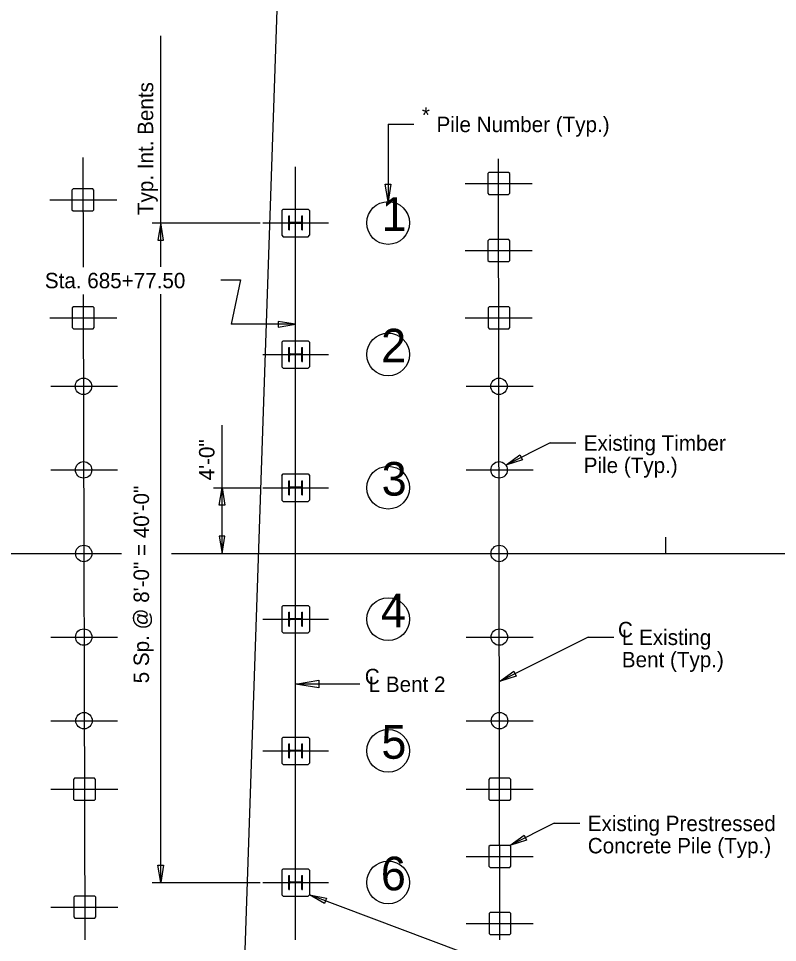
# Model space of a CAD drawing. Extents: x -463 to -191, y 251 to 416.
# Drawn here: x -363.8 to -317.7, y 310.9 to 367.1 of the extents above; entities that cross this region are included whole.
import ezdxf

# ---------------------------------------------------------------- set-up
doc = ezdxf.new("R2010")
doc.units = 0
for name, color, linetype in [('BR_AUTO DIMENSION', 7, 'Continuous'), ('BR_CONCRETE', 7, 'Continuous'), ('BR_STRUCTURAL STEEL', 7, 'Continuous'), ('BR_TEXT', 7, 'Continuous'), ('Default', 7, 'Continuous')]:
    doc.layers.add(name, color=color, linetype=linetype)

msp = doc.modelspace()

# ---------------------------------------------------------------- linework, layer by layer
at = {"layer": 'BR_AUTO DIMENSION'}
for p, q in [((-355.142, 352.015), (-355.142, 366.063)), ((-341.324, 360.69), (-339.764, 360.69)), ((-341.324, 360.69), (-341.324, 355.984)), ((-341.5, 357.038), (-341.148, 357.039)), ((-341.324, 355.984), (-341.5, 357.038)), ((-341.148, 357.039), (-341.324, 355.984)), ((-355.654, 354.684), (-349.094, 354.684)), ((-355.142, 354.684), (-355.318, 353.629)), ((-354.966, 353.629), (-355.142, 354.684)), ((-355.318, 353.629), (-354.966, 353.629)), ((-351.49, 351.228), (-350.302, 351.228)), ((-350.302, 351.228), (-350.858, 348.523)), ((-355.142, 314.588), (-355.142, 350.351)), ((-346.942, 348.523), (-350.858, 348.523)), ((-346.942, 348.523), (-347.997, 348.699)), ((-347.997, 348.699), (-347.997, 348.347)), ((-347.997, 348.347), (-346.942, 348.523)), ((-351.417, 334.588), (-351.417, 342.399)), ((-331.475, 341.314), (-334.173, 339.965)), ((-331.475, 341.314), (-329.915, 341.314)), ((-334.173, 339.965), (-333.309, 340.594)), ((-333.309, 340.594), (-333.151, 340.28)), ((-333.151, 340.28), (-334.173, 339.965)), ((-351.928, 338.588), (-349.094, 338.588)), ((-351.593, 337.532), (-351.417, 338.588)), ((-351.417, 338.588), (-351.241, 337.533)), ((-351.241, 337.533), (-351.593, 337.532)), ((-351.241, 335.642), (-351.593, 335.643)), ((-351.593, 335.643), (-351.417, 334.588)), ((-351.417, 334.588), (-351.241, 335.642)), ((-329.159, 329.503), (-334.555, 326.805)), ((-329.159, 329.503), (-327.599, 329.503)), ((-334.555, 326.805), (-333.691, 327.434)), ((-333.533, 327.119), (-334.555, 326.805)), ((-333.691, 327.434), (-333.533, 327.119)), ((-346.942, 326.643), (-345.536, 326.878)), ((-343.034, 326.643), (-346.942, 326.643)), ((-345.535, 326.409), (-346.942, 326.643)), ((-345.536, 326.878), (-345.535, 326.409)), ((-331.23, 318.187), (-333.928, 316.838)), ((-331.23, 318.187), (-329.67, 318.187)), ((-333.928, 316.838), (-333.063, 317.467)), ((-333.063, 317.467), (-332.905, 317.152)), ((-332.905, 317.152), (-333.928, 316.838)), ((-355.318, 315.642), (-354.966, 315.643)), ((-355.142, 314.588), (-355.318, 315.642)), ((-354.966, 315.643), (-355.142, 314.588)), ((-355.654, 314.588), (-349.094, 314.588)), ((-334.693, 309.546), (-346.109, 313.838)), ((-346.109, 313.838), (-345.059, 313.631)), ((-345.183, 313.302), (-346.109, 313.838)), ((-345.059, 313.631), (-345.183, 313.302))]:
    msp.add_line(p, q, dxfattribs=at)
for centre in [(-341.324, 354.684), (-341.324, 346.684), (-341.324, 338.588), (-341.324, 330.588), (-341.324, 322.588), (-341.324, 314.588)]:
    msp.add_circle(centre, 1.3, dxfattribs=at)
at = {"layer": 'BR_CONCRETE'}
for p, q in [((-347.775, 355.434), (-347.692, 355.517)), ((-347.775, 355.434), (-347.775, 353.934)), ((-347.692, 355.517), (-346.192, 355.517)), ((-346.192, 355.517), (-346.109, 355.434)), ((-346.109, 355.434), (-346.109, 353.934)), ((-347.775, 353.934), (-347.692, 353.851)), ((-347.692, 353.851), (-346.192, 353.851)), ((-346.192, 353.851), (-346.109, 353.934)), ((-347.775, 347.434), (-347.692, 347.517)), ((-347.775, 347.434), (-347.775, 345.934)), ((-347.692, 347.517), (-346.192, 347.517)), ((-346.192, 347.517), (-346.109, 347.434)), ((-346.109, 347.434), (-346.109, 345.934)), ((-347.775, 345.934), (-347.692, 345.851)), ((-347.692, 345.851), (-346.192, 345.851)), ((-346.192, 345.851), (-346.109, 345.934)), ((-347.775, 339.338), (-347.692, 339.421)), ((-347.692, 339.421), (-346.192, 339.421)), ((-346.192, 339.421), (-346.109, 339.338)), ((-347.775, 339.338), (-347.775, 337.838)), ((-346.109, 339.338), (-346.109, 337.838)), ((-347.775, 337.838), (-347.692, 337.754)), ((-347.692, 337.754), (-346.192, 337.754)), ((-346.192, 337.754), (-346.109, 337.838)), ((-347.775, 331.338), (-347.692, 331.421)), ((-347.775, 331.338), (-347.775, 329.838)), ((-347.692, 331.421), (-346.192, 331.421)), ((-346.192, 331.421), (-346.109, 331.338)), ((-346.109, 331.338), (-346.109, 329.838)), ((-347.775, 329.838), (-347.692, 329.754)), ((-346.192, 329.754), (-346.109, 329.838)), ((-347.692, 329.754), (-346.192, 329.754)), ((-347.775, 323.338), (-347.692, 323.421)), ((-347.775, 323.338), (-347.775, 321.838)), ((-347.692, 323.421), (-346.192, 323.421)), ((-346.192, 323.421), (-346.109, 323.338)), ((-346.109, 323.338), (-346.109, 321.838)), ((-347.775, 321.838), (-347.692, 321.754)), ((-347.692, 321.754), (-346.192, 321.754)), ((-346.192, 321.754), (-346.109, 321.838)), ((-347.775, 315.338), (-347.692, 315.421)), ((-347.775, 315.338), (-347.775, 313.838)), ((-347.692, 315.421), (-346.192, 315.421)), ((-346.192, 315.421), (-346.109, 315.338)), ((-346.109, 315.338), (-346.109, 313.838)), ((-347.775, 313.838), (-347.692, 313.754)), ((-347.692, 313.754), (-346.192, 313.754)), ((-346.192, 313.754), (-346.109, 313.838))]:
    msp.add_line(p, q, dxfattribs=at)
for points in [[(-335.264, 356.488), (-335.197, 356.421), (-333.997, 356.421), (-333.931, 356.488), (-333.931, 357.688), (-333.997, 357.754), (-335.197, 357.754), (-335.264, 357.688)], [(-360.537, 355.488), (-360.47, 355.421), (-359.27, 355.421), (-359.203, 355.488), (-359.203, 356.688), (-359.27, 356.754), (-360.47, 356.754), (-360.537, 356.688)], [(-335.257, 352.404), (-335.19, 352.338), (-333.99, 352.338), (-333.924, 352.404), (-333.924, 353.604), (-333.99, 353.671), (-335.19, 353.671), (-335.257, 353.604)], [(-360.516, 348.321), (-360.449, 348.254), (-359.249, 348.254), (-359.182, 348.321), (-359.182, 349.521), (-359.249, 349.588), (-360.449, 349.588), (-360.516, 349.521)], [(-335.25, 348.321), (-335.183, 348.254), (-333.983, 348.254), (-333.917, 348.321), (-333.917, 349.521), (-333.983, 349.588), (-335.183, 349.588), (-335.25, 349.521)], [(-360.442, 319.654), (-360.375, 319.588), (-359.175, 319.588), (-359.109, 319.654), (-359.109, 320.854), (-359.175, 320.921), (-360.375, 320.921), (-360.442, 320.854)], [(-335.201, 319.654), (-335.135, 319.588), (-333.935, 319.588), (-333.868, 319.654), (-333.868, 320.854), (-333.935, 320.921), (-335.135, 320.921), (-335.201, 320.854)], [(-335.194, 315.571), (-335.128, 315.504), (-333.928, 315.504), (-333.861, 315.571), (-333.861, 316.771), (-333.928, 316.838), (-335.128, 316.838), (-335.194, 316.771)], [(-360.421, 312.488), (-360.354, 312.421), (-359.154, 312.421), (-359.088, 312.488), (-359.088, 313.688), (-359.154, 313.754), (-360.354, 313.754), (-360.421, 313.688)], [(-335.187, 311.488), (-335.121, 311.421), (-333.921, 311.421), (-333.854, 311.488), (-333.854, 312.688), (-333.921, 312.754), (-335.121, 312.754), (-335.187, 312.688)]]:
    msp.add_lwpolyline(points, close=True, dxfattribs=at)
for centre in [(-359.839, 344.754), (-334.586, 344.754), (-359.831, 339.671), (-334.577, 339.671), (-359.822, 334.588), (-334.569, 334.588), (-359.822, 329.504), (-334.56, 329.504), (-359.805, 324.421), (-334.551, 324.421)]:
    msp.add_circle(centre, 0.5, dxfattribs=at)
at = {"layer": 'BR_STRUCTURAL STEEL'}
for p, q in [((-347.358, 354.258), (-347.358, 355.11)), ((-347.358, 355.11), (-347.311, 355.11)), ((-347.311, 354.752), (-347.311, 355.11)), ((-346.573, 355.11), (-346.526, 355.11)), ((-346.573, 354.752), (-346.573, 355.11)), ((-346.526, 354.258), (-346.526, 355.11)), ((-347.311, 354.258), (-347.311, 354.616)), ((-346.625, 354.707), (-347.259, 354.707)), ((-346.625, 354.661), (-347.259, 354.661)), ((-346.573, 354.258), (-346.573, 354.616)), ((-347.358, 354.258), (-347.311, 354.258)), ((-346.573, 354.258), (-346.526, 354.258)), ((-347.358, 346.258), (-347.358, 347.11)), ((-347.358, 347.11), (-347.311, 347.11)), ((-347.311, 346.752), (-347.311, 347.11)), ((-346.625, 346.707), (-347.259, 346.707)), ((-346.625, 346.661), (-347.259, 346.661)), ((-346.573, 347.11), (-346.526, 347.11)), ((-346.573, 346.752), (-346.573, 347.11)), ((-346.526, 346.258), (-346.526, 347.11)), ((-347.358, 346.258), (-347.311, 346.258)), ((-347.311, 346.258), (-347.311, 346.616)), ((-346.573, 346.258), (-346.573, 346.616)), ((-346.573, 346.258), (-346.526, 346.258)), ((-347.358, 338.162), (-347.358, 339.014)), ((-347.358, 339.014), (-347.311, 339.014)), ((-347.311, 338.655), (-347.311, 339.014)), ((-346.573, 339.014), (-346.526, 339.014)), ((-346.573, 338.655), (-346.573, 339.014)), ((-346.526, 338.162), (-346.526, 339.014)), ((-347.311, 338.162), (-347.311, 338.52)), ((-346.625, 338.611), (-347.259, 338.611)), ((-346.625, 338.564), (-347.259, 338.564)), ((-346.573, 338.162), (-346.573, 338.52)), ((-347.358, 338.162), (-347.311, 338.162)), ((-346.573, 338.162), (-346.526, 338.162)), ((-347.358, 330.162), (-347.358, 331.014)), ((-347.358, 331.014), (-347.311, 331.014)), ((-347.311, 330.655), (-347.311, 331.014)), ((-346.573, 331.014), (-346.526, 331.014)), ((-346.573, 330.655), (-346.573, 331.014)), ((-346.526, 330.162), (-346.526, 331.014)), ((-347.311, 330.162), (-347.311, 330.52)), ((-346.625, 330.611), (-347.259, 330.611)), ((-346.625, 330.564), (-347.259, 330.564)), ((-346.573, 330.162), (-346.573, 330.52)), ((-347.358, 330.162), (-347.311, 330.162)), ((-346.573, 330.162), (-346.526, 330.162)), ((-347.358, 322.162), (-347.358, 323.014)), ((-347.358, 323.014), (-347.311, 323.014)), ((-347.311, 322.655), (-347.311, 323.014)), ((-347.311, 322.162), (-347.311, 322.52)), ((-346.625, 322.611), (-347.259, 322.611)), ((-346.625, 322.564), (-347.259, 322.564)), ((-346.573, 323.014), (-346.526, 323.014)), ((-346.573, 322.655), (-346.573, 323.014)), ((-346.573, 322.162), (-346.573, 322.52)), ((-346.526, 322.162), (-346.526, 323.014)), ((-347.358, 322.162), (-347.311, 322.162)), ((-346.573, 322.162), (-346.526, 322.162)), ((-347.358, 314.162), (-347.358, 315.014)), ((-347.358, 315.014), (-347.311, 315.014)), ((-347.311, 314.655), (-347.311, 315.014)), ((-346.573, 315.014), (-346.526, 315.014)), ((-346.573, 314.655), (-346.573, 315.014)), ((-346.526, 314.162), (-346.526, 315.014)), ((-347.358, 314.162), (-347.311, 314.162)), ((-347.311, 314.162), (-347.311, 314.52)), ((-346.625, 314.611), (-347.259, 314.611)), ((-346.625, 314.564), (-347.259, 314.564)), ((-346.573, 314.162), (-346.573, 314.52)), ((-346.573, 314.162), (-346.526, 314.162))]:
    msp.add_line(p, q, dxfattribs=at)
for centre, start, end in [((-347.259, 354.76), 180, 270), ((-347.259, 354.609), 90, 180), ((-346.625, 354.76), 270, 360), ((-346.625, 354.609), 360, 90), ((-347.259, 346.76), 180, 270), ((-347.259, 346.609), 90, 180), ((-346.625, 346.76), 270, 360), ((-346.625, 346.609), 360, 90), ((-347.259, 338.663), 180, 270), ((-347.259, 338.512), 90, 180), ((-346.625, 338.663), 270, 360), ((-346.625, 338.512), 360, 90), ((-347.259, 330.663), 180, 270), ((-347.259, 330.512), 90, 180), ((-346.625, 330.663), 270, 360), ((-346.625, 330.512), 360, 90), ((-347.259, 322.663), 180, 270), ((-347.259, 322.512), 90, 180), ((-346.625, 322.663), 270, 360), ((-346.625, 322.512), 360, 90), ((-347.259, 314.663), 180, 270), ((-346.625, 314.663), 270, 360), ((-347.259, 314.512), 90, 180), ((-346.625, 314.512), 360, 90)]:
    msp.add_arc(centre, 0.0521, start, end, dxfattribs=at)
at = {"layer": 'Default'}
for p, q in [((-359.884, 358.674), (-359.867, 352.003)), ((-334.607, 357.124), (-334.61, 358.588)), ((-346.942, 311.088), (-346.942, 358.088)), ((-336.631, 357.088), (-332.564, 357.088)), ((-334.529, 311.088), (-334.607, 357.088)), ((-361.885, 356.088), (-357.817, 356.088)), ((-348.942, 354.684), (-344.942, 354.684)), ((-336.631, 353.004), (-332.564, 353.004)), ((-359.862, 350.339), (-359.761, 311.088)), ((-361.885, 348.921), (-357.817, 348.921)), ((-336.631, 348.921), (-332.564, 348.921)), ((-348.942, 346.684), (-344.942, 346.684)), ((-361.829, 344.754), (-357.761, 344.754)), ((-336.575, 344.754), (-332.508, 344.754)), ((-361.829, 339.671), (-357.761, 339.671)), ((-336.575, 339.671), (-332.508, 339.671)), ((-348.942, 338.588), (-344.942, 338.588)), ((-324.439, 334.588), (-324.439, 335.588)), ((-378.583, 334.588), (-357.519, 334.588)), ((-361.829, 334.588), (-357.761, 334.588)), ((-354.498, 334.588), (-196.63, 334.588)), ((-336.575, 334.588), (-332.508, 334.588)), ((-348.942, 330.588), (-344.942, 330.588)), ((-361.829, 329.504), (-357.761, 329.504)), ((-336.575, 329.504), (-332.508, 329.504)), ((-361.829, 324.421), (-357.761, 324.421)), ((-336.575, 324.421), (-332.508, 324.421)), ((-348.942, 322.588), (-344.942, 322.588)), ((-361.827, 320.254), (-357.759, 320.254)), ((-336.574, 320.254), (-332.506, 320.254)), ((-336.574, 316.171), (-332.506, 316.171)), ((-348.942, 314.588), (-344.942, 314.588)), ((-361.827, 313.088), (-357.759, 313.088)), ((-336.574, 312.088), (-332.506, 312.088))]:
    msp.add_line(p, q, dxfattribs=at)
msp.add_lwpolyline([(-350.569, 293.783), (-348.075, 367.639), (-357.521, 375.932), (-398.853, 389.643)], dxfattribs=at)

# ---------------------------------------------------------------- texts
at = {"layer": 'BR_TEXT'}
for s, p in [('Typ. Int. Bents', (-355.601, 355.167)), ('4\'-0"', (-351.879, 339.036)), ('5 Sp. @ 8\'-0" = 40\'-0"', (-355.855, 326.693))]:
    msp.add_text(s, height=0.9375, rotation=90, dxfattribs=at).set_placement(p)
for s, height, p in [('*', 0.938, (-339.271, 360.779)), ('Pile Number (Typ.)', 0.9375, (-338.379, 360.208)), ('1', 2.045, (-341.716, 354.204)), ('Sta. 685+77.50', 0.9375, (-362.186, 350.714)), ('2', 2.045, (-341.748, 346.204)), ('Existing Timber', 0.9375, (-329.433, 340.832)), ('3', 2.045, (-341.716, 338.107)), ('Pile (Typ.)', 0.9375, (-329.433, 339.482)), ('4', 2.045, (-341.764, 330.107)), ('C', 0.938, (-327.353, 329.49)), ('L Existing ', 0.9375, (-327.117, 329.021)), ('Bent (Typ.)', 0.9375, (-327.117, 327.67)), ('C', 0.938, (-342.74, 326.637)), ('L Bent 2', 0.9375, (-342.504, 326.168)), ('5', 2.045, (-341.732, 322.107)), ('Existing Prestressed ', 0.9375, (-329.187, 317.705)), ('Concrete Pile (Typ.)', 0.9375, (-329.187, 316.354)), ('6', 2.045, (-341.764, 314.107))]:
    msp.add_text(s, height=height, dxfattribs=at).set_placement(p)

doc.saveas('drawing.dxf')
